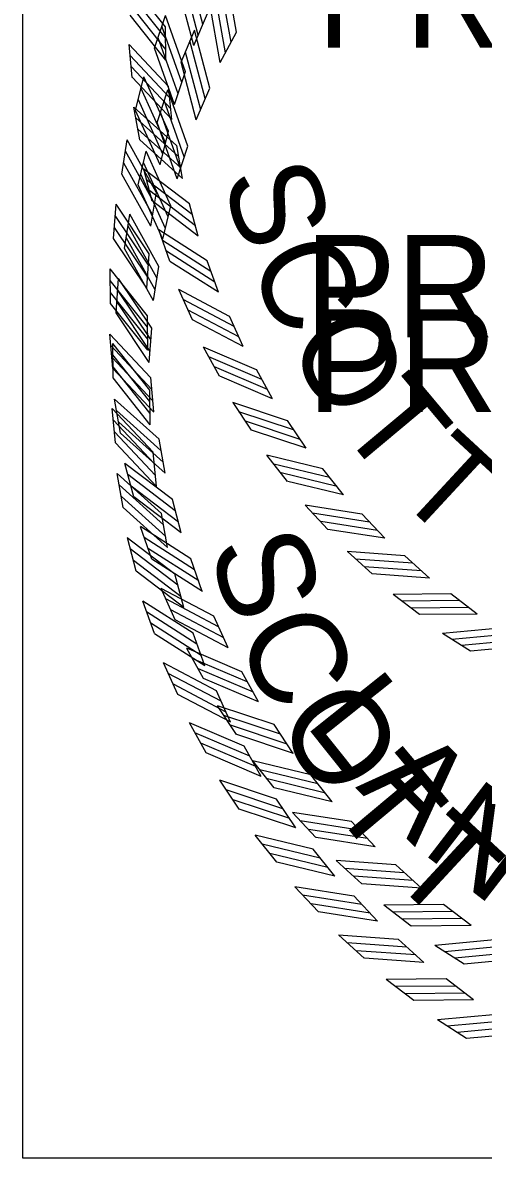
# Model space of a CAD drawing. Extents: x 0 to 1228740, y 0 to 152440.
# Drawn here: x 30.673 to 31.399, y 22.685 to 24.476 of the extents above; entities that cross this region are included whole.
import ezdxf

# ---------------------------------------------------------------- set-up
doc = ezdxf.new("R2010")
doc.units = 0
for name, color, linetype in [('R_No Plot', 7, 'Continuous'), ('STAMP_LKM', 7, 'Continuous'), ('STAMP_PP', 7, 'Continuous'), ('STAMP_SPT', 7, 'Continuous')]:
    doc.layers.add(name, color=color, linetype=linetype)

msp = doc.modelspace()

# ---------------------------------------------------------------- linework, layer by layer
at = {"layer": 'R_No Plot'}
msp.add_lwpolyline([(30.6731, 25.4352), (33.4231, 25.4352), (33.4231, 22.6852), (30.6731, 22.6852)], close=True, dxfattribs=at)
at = {"layer": 'STAMP_LKM'}
for p, q in [((30.8808, 24.4356), (30.898, 24.4872)), ((30.9426, 24.4399), (30.964, 24.49)), ((30.851, 24.3374), (30.8639, 24.3903)), ((30.9122, 24.3468), (30.9295, 24.3986)), ((30.8897, 24.2516), (30.9026, 24.3046)), ((30.8295, 24.2371), (30.8379, 24.2909)), ((30.8751, 24.1548), (30.8836, 24.2087)), ((30.8162, 24.1354), (30.8202, 24.1897)), ((30.8685, 24.0571), (30.8725, 24.1115)), ((30.8115, 24.033), (30.811, 24.0874)), ((30.8701, 23.9593), (30.8696, 24.0138)), ((30.8152, 23.9305), (30.8102, 23.9847)), ((30.8797, 23.8619), (30.8747, 23.9162)), ((30.8274, 23.8287), (30.8179, 23.8822)), ((30.8973, 23.7656), (30.8878, 23.8193)), ((30.8479, 23.7282), (30.8341, 23.7808)), ((30.9228, 23.6711), (30.9089, 23.7238)), ((30.8767, 23.6297), (30.8585, 23.681)), ((30.956, 23.579), (30.9378, 23.6305)), ((30.9135, 23.534), (30.8911, 23.5836)), ((30.9967, 23.49), (30.9743, 23.5398)), ((30.958, 23.4416), (30.9317, 23.4892)), ((31.0446, 23.4047), (31.0182, 23.4524)), ((31.0101, 23.3533), (30.9799, 23.3985)), ((31.0994, 23.3236), (31.0692, 23.369)), ((31.0692, 23.2695), (31.0354, 23.3121)), ((31.1607, 23.2473), (31.1269, 23.29)), ((31.1351, 23.1909), (31.0979, 23.2306)), ((31.2282, 23.1763), (31.1908, 23.2161)), ((31.2073, 23.118), (31.1669, 23.1545)), ((31.3012, 23.1112), (31.2607, 23.1477)), ((31.2852, 23.0513), (31.242, 23.0843)), ((31.3794, 23.0523), (31.336, 23.0854)), ((31.3684, 22.9913), (31.3225, 23.0206))]:
    msp.add_line(p, q, dxfattribs=at)
for points in [[(30.9567, 24.4734), (30.9326, 24.5644)], [(30.9426, 24.4398), (30.9186, 24.5308)], [(30.9496, 24.4558), (30.9256, 24.5469)], [(30.9294, 24.3985), (30.8979, 24.4872)], [(30.9235, 24.3814), (30.8921, 24.4701)], [(30.918, 24.3633), (30.8865, 24.452)], [(30.9123, 24.3467), (30.8808, 24.4355)], [(30.9025, 24.3045), (30.8639, 24.3903)], [(30.8981, 24.2869), (30.8594, 24.3728)], [(30.894, 24.2685), (30.8553, 24.3543)], [(30.8897, 24.2515), (30.851, 24.3373)], [(30.8835, 24.2086), (30.8379, 24.2909)], [(30.8805, 24.1907), (30.8349, 24.2731)], [(30.878, 24.172), (30.8324, 24.2543)], [(30.8751, 24.1547), (30.8295, 24.2371)], [(30.8725, 24.1115), (30.8202, 24.1898)], [(30.871, 24.0934), (30.8187, 24.1717)], [(30.87, 24.0745), (30.8177, 24.1528)], [(30.8686, 24.0571), (30.8163, 24.1354)], [(30.8695, 24.0137), (30.8109, 24.0874)], [(30.8695, 23.9956), (30.8109, 24.0693)], [(30.8701, 23.9767), (30.8115, 24.0504)], [(30.8701, 23.9592), (30.8115, 24.0329)], [(30.8746, 23.9161), (30.8102, 23.9847)], [(30.8761, 23.8981), (30.8117, 23.9667)], [(30.8783, 23.8793), (30.8138, 23.9479)], [(30.8797, 23.8618), (30.8153, 23.9304)], [(30.8878, 23.8192), (30.8179, 23.8823)], [(30.8908, 23.8014), (30.8209, 23.8644)], [(30.8945, 23.7828), (30.8246, 23.8459)], [(30.8973, 23.7655), (30.8274, 23.8286)], [(30.9089, 23.7238), (30.834, 23.7808)], [(30.9133, 23.7062), (30.8385, 23.7633)], [(30.9186, 23.688), (30.8437, 23.7451)], [(30.9228, 23.6711), (30.848, 23.7281)], [(30.9378, 23.6304), (30.8585, 23.6811)], [(30.9437, 23.6132), (30.8644, 23.6639)], [(30.9504, 23.5956), (30.8711, 23.6462)], [(30.9561, 23.579), (30.8767, 23.6297)], [(30.9743, 23.5397), (30.8911, 23.5837)], [(30.9816, 23.5231), (30.8984, 23.5671)], [(30.9898, 23.506), (30.9065, 23.55)], [(30.9968, 23.49), (30.9135, 23.534)], [(31.0182, 23.4523), (30.9316, 23.4893)], [(31.0269, 23.4364), (30.9403, 23.4733)], [(31.0364, 23.4201), (30.9498, 23.457)], [(31.0447, 23.4047), (30.9581, 23.4416)], [(31.0692, 23.3689), (30.9798, 23.3986)], [(31.0791, 23.3537), (30.9898, 23.3834)], [(31.0899, 23.3382), (31.0006, 23.3679)], [(31.0995, 23.3236), (31.0102, 23.3532)], [(31.1269, 23.29), (31.0354, 23.3121)], [(31.138, 23.2757), (31.0465, 23.2978)], [(31.1501, 23.2611), (31.0586, 23.2833)], [(31.1608, 23.2473), (31.0693, 23.2695)], [(31.1909, 23.216), (31.0979, 23.2306)], [(31.2031, 23.2027), (31.1101, 23.2173)], [(31.2164, 23.1892), (31.1234, 23.2038)], [(31.2282, 23.1763), (31.1352, 23.1909)], [(31.2607, 23.1477), (31.1669, 23.1545)], [(31.2741, 23.1354), (31.1802, 23.1422)], [(31.2884, 23.123), (31.1945, 23.1299)], [(31.3013, 23.1112), (31.2074, 23.118)], [(31.336, 23.0853), (31.2419, 23.0843)], [(31.3503, 23.0742), (31.2562, 23.0732)], [(31.3656, 23.063), (31.2715, 23.0621)], [(31.3794, 23.0523), (31.2853, 23.0513)], [(31.4162, 23.0294), (31.3225, 23.0206)], [(31.4314, 23.0195), (31.3377, 23.0107)], [(31.4475, 23.0096), (31.3538, 23.0009)], [(31.4622, 23), (31.3685, 22.9913)]]:
    msp.add_lwpolyline(points, dxfattribs=at)
at = {"layer": 'STAMP_PP'}
for p, q in [((30.8986, 24.4169), (30.8981, 24.4694)), ((30.8457, 24.3891), (30.8409, 24.4413)), ((30.9078, 24.323), (30.903, 24.3754)), ((30.8574, 24.2911), (30.8483, 24.3427)), ((30.9248, 24.2303), (30.9157, 24.282)), ((30.8772, 24.1943), (30.8639, 24.245)), ((30.9493, 24.1393), (30.936, 24.1901)), ((30.9049, 24.0995), (30.8875, 24.1489)), ((30.9813, 24.0506), (30.9638, 24.1002)), ((30.9404, 24.0073), (30.9189, 24.0551)), ((31.0205, 23.9649), (30.999, 24.0128)), ((30.9833, 23.9183), (30.9579, 23.9642)), ((31.0667, 23.8827), (31.0413, 23.9287)), ((31.0334, 23.8332), (31.0044, 23.8768)), ((31.1195, 23.8046), (31.0903, 23.8483)), ((31.0904, 23.7525), (31.0578, 23.7936)), ((31.1785, 23.7311), (31.1459, 23.7723)), ((31.1539, 23.6768), (31.118, 23.715)), ((31.2435, 23.6628), (31.2075, 23.7011)), ((31.2234, 23.6066), (31.1845, 23.6417)), ((31.3138, 23.6), (31.2748, 23.6352)), ((31.2984, 23.5424), (31.2568, 23.5742)), ((31.3891, 23.5433), (31.3473, 23.5752)), ((31.3785, 23.4846), (31.3344, 23.5128))]:
    msp.add_line(p, q, dxfattribs=at)
for points in [[(30.898, 24.4693), (30.8416, 24.5403)], [(30.898, 24.4519), (30.8416, 24.5228)], [(30.8986, 24.4337), (30.8422, 24.5046)], [(30.8986, 24.4168), (30.8422, 24.4878)], [(30.903, 24.3753), (30.8409, 24.4414)], [(30.9044, 24.3579), (30.8423, 24.424)], [(30.9065, 24.3398), (30.8444, 24.4059)], [(30.9079, 24.323), (30.8458, 24.3891)], [(30.9156, 24.282), (30.8483, 24.3427)], [(30.9185, 24.2648), (30.8512, 24.3255)], [(30.9221, 24.2469), (30.8547, 24.3076)], [(30.9248, 24.2303), (30.8575, 24.291)], [(30.936, 24.19), (30.8638, 24.245)], [(30.9402, 24.1731), (30.8681, 24.2281)], [(30.9453, 24.1556), (30.8731, 24.2106)], [(30.9494, 24.1393), (30.8773, 24.1942)], [(30.9638, 24.1001), (30.8874, 24.1489)], [(30.9695, 24.0836), (30.8931, 24.1324)], [(30.9759, 24.0665), (30.8995, 24.1154)], [(30.9814, 24.0506), (30.905, 24.0994)], [(30.999, 24.0127), (30.9188, 24.0551)], [(31.006, 23.9968), (30.9258, 24.0391)], [(31.0138, 23.9803), (30.9337, 24.0227)], [(31.0206, 23.9649), (30.9404, 24.0072)], [(31.0413, 23.9286), (30.9579, 23.9642)], [(31.0496, 23.9133), (30.9662, 23.9488)], [(31.0587, 23.8975), (30.9753, 23.9331)], [(31.0668, 23.8827), (30.9834, 23.9183)], [(31.0904, 23.8482), (31.0043, 23.8768)], [(31.0999, 23.8336), (31.0138, 23.8622)], [(31.1103, 23.8187), (31.0243, 23.8473)], [(31.1196, 23.8046), (31.0335, 23.8332)], [(31.1459, 23.7722), (31.0578, 23.7936)], [(31.1566, 23.7584), (31.0685, 23.7798)], [(31.1683, 23.7444), (31.0801, 23.7658)], [(31.1786, 23.7311), (31.0905, 23.7525)], [(31.2075, 23.701), (31.118, 23.715)], [(31.2194, 23.6882), (31.1298, 23.7022)], [(31.2321, 23.6752), (31.1425, 23.6892)], [(31.2435, 23.6628), (31.1539, 23.6768)], [(31.2748, 23.6352), (31.1844, 23.6417)], [(31.2877, 23.6234), (31.1973, 23.6299)], [(31.3015, 23.6114), (31.211, 23.618)], [(31.3139, 23.6), (31.2234, 23.6066)], [(31.3474, 23.5751), (31.2567, 23.5742)], [(31.3611, 23.5644), (31.2705, 23.5635)], [(31.3758, 23.5537), (31.2852, 23.5527)], [(31.3892, 23.5433), (31.2985, 23.5424)], [(31.4246, 23.5212), (31.3343, 23.5128)], [(31.4392, 23.5117), (31.3489, 23.5033)], [(31.4547, 23.5022), (31.3645, 23.4938)], [(31.4689, 23.493), (31.3786, 23.4846)]]:
    msp.add_lwpolyline(points, dxfattribs=at)
at = {"layer": 'STAMP_SPT'}
for p, q in [((30.9225, 24.4136), (30.9439, 24.4636)), ((30.9844, 24.4128), (31.0099, 24.461)), ((30.8847, 24.3182), (30.9019, 24.3698)), ((30.9465, 24.3225), (30.968, 24.3727)), ((30.9162, 24.2295), (30.9334, 24.2812)), ((30.8549, 24.2201), (30.8678, 24.2729)), ((30.8334, 24.1198), (30.8418, 24.1735)), ((30.8936, 24.1342), (30.9065, 24.1872)), ((30.879, 24.0375), (30.8875, 24.0913)), ((30.8202, 24.0181), (30.8242, 24.0724)), ((30.8725, 23.9398), (30.8765, 23.9942)), ((30.8154, 23.9156), (30.8149, 23.9701)), ((30.874, 23.8419), (30.8735, 23.8965)), ((30.8191, 23.8132), (30.8141, 23.8673)), ((30.8836, 23.7445), (30.8786, 23.7988)), ((30.8313, 23.7113), (30.8219, 23.7649)), ((30.9012, 23.6483), (30.8917, 23.702)), ((30.8518, 23.6108), (30.838, 23.6635)), ((30.9267, 23.5538), (30.9128, 23.6065)), ((30.8806, 23.5124), (30.8625, 23.5637)), ((30.9599, 23.4617), (30.9418, 23.5131)), ((30.9174, 23.4167), (30.8951, 23.4663)), ((31.0006, 23.3727), (30.9783, 23.4224)), ((30.962, 23.3243), (30.9356, 23.3719)), ((31.0486, 23.2873), (31.0222, 23.3351)), ((31.014, 23.2359), (30.9838, 23.2812)), ((31.1034, 23.2063), (31.0731, 23.2516)), ((31.0732, 23.1522), (31.0394, 23.1948)), ((31.1647, 23.13), (31.1308, 23.1727)), ((31.1391, 23.0736), (31.1019, 23.1132)), ((31.2321, 23.059), (31.1948, 23.0988)), ((31.2112, 23.0007), (31.1709, 23.0371)), ((31.3051, 22.9938), (31.2647, 23.0304)), ((31.2891, 22.934), (31.2459, 22.967)), ((31.3833, 22.9349), (31.3399, 22.968)), ((31.3723, 22.874), (31.3265, 22.9033))]:
    msp.add_line(p, q, dxfattribs=at)
for points in [[(31.0099, 24.4609), (30.9934, 24.5536)], [(31.0013, 24.445), (30.9848, 24.5377)], [(30.9928, 24.4281), (30.9763, 24.5208)], [(30.9844, 24.4127), (30.968, 24.5054)], [(30.9679, 24.3726), (30.9439, 24.4637)], [(30.9606, 24.356), (30.9366, 24.4471)], [(30.9536, 24.3385), (30.9295, 24.4295)], [(30.9465, 24.3225), (30.9225, 24.4135)], [(30.9334, 24.2812), (30.9019, 24.3699)], [(30.9275, 24.264), (30.896, 24.3528)], [(30.9219, 24.246), (30.8904, 24.3347)], [(30.9162, 24.2294), (30.8847, 24.3181)], [(30.9065, 24.1872), (30.8678, 24.273)], [(30.902, 24.1696), (30.8633, 24.2554)], [(30.898, 24.1511), (30.8593, 24.237)], [(30.8937, 24.1342), (30.855, 24.22)], [(30.8875, 24.0913), (30.8418, 24.1736)], [(30.8845, 24.0734), (30.8388, 24.1557)], [(30.882, 24.0547), (30.8363, 24.137)], [(30.8791, 24.0374), (30.8334, 24.1197)], [(30.8764, 23.9941), (30.8241, 24.0724)], [(30.8749, 23.9761), (30.8226, 24.0543)], [(30.874, 23.9572), (30.8217, 24.0355)], [(30.8725, 23.9397), (30.8202, 24.018)], [(30.8735, 23.8964), (30.8149, 23.9701)], [(30.8735, 23.8783), (30.8149, 23.952)], [(30.8741, 23.8594), (30.8155, 23.9331)], [(30.8741, 23.8419), (30.8155, 23.9156)], [(30.8786, 23.7988), (30.8141, 23.8674)], [(30.8801, 23.7807), (30.8156, 23.8493)], [(30.8822, 23.7619), (30.8177, 23.8305)], [(30.8837, 23.7445), (30.8192, 23.8131)], [(30.8917, 23.7019), (30.8218, 23.7649)], [(30.8947, 23.684), (30.8248, 23.7471)], [(30.8984, 23.6655), (30.8285, 23.7285)], [(30.9013, 23.6482), (30.8314, 23.7113)], [(30.9128, 23.6064), (30.8379, 23.6635)], [(30.9173, 23.5889), (30.8424, 23.6459)], [(30.9225, 23.5707), (30.8476, 23.6278)], [(30.9268, 23.5537), (30.8519, 23.6108)], [(30.9417, 23.513), (30.8624, 23.5637)], [(30.9476, 23.4959), (30.8683, 23.5466)], [(30.9543, 23.4782), (30.875, 23.5289)], [(30.96, 23.4617), (30.8807, 23.5123)], [(30.9783, 23.4224), (30.895, 23.4663)], [(30.9856, 23.4058), (30.9023, 23.4497)], [(30.9937, 23.3887), (30.9104, 23.4327)], [(31.0007, 23.3727), (30.9175, 23.4166)], [(31.0222, 23.335), (30.9356, 23.3719)], [(31.0308, 23.3191), (30.9442, 23.356)], [(31.0403, 23.3027), (30.9537, 23.3397)], [(31.0486, 23.2873), (30.962, 23.3243)], [(31.0731, 23.2516), (30.9838, 23.2812)], [(31.083, 23.2364), (30.9937, 23.266)], [(31.0939, 23.2209), (31.0045, 23.2505)], [(31.1034, 23.2062), (31.0141, 23.2359)], [(31.1308, 23.1726), (31.0393, 23.1948)], [(31.1419, 23.1583), (31.0504, 23.1805)], [(31.154, 23.1438), (31.0625, 23.1659)], [(31.1648, 23.1299), (31.0733, 23.1521)], [(31.1948, 23.0987), (31.1018, 23.1133)], [(31.2071, 23.0854), (31.1141, 23.0999)], [(31.2203, 23.0719), (31.1273, 23.0864)], [(31.2322, 23.059), (31.1392, 23.0735)], [(31.2647, 23.0303), (31.1708, 23.0372)], [(31.278, 23.0181), (31.1841, 23.0249)], [(31.2923, 23.0057), (31.1984, 23.0125)], [(31.3052, 22.9938), (31.2113, 23.0007)], [(31.34, 22.968), (31.2458, 22.967)], [(31.3543, 22.9568), (31.2601, 22.9559)], [(31.3695, 22.9457), (31.2754, 22.9447)], [(31.3834, 22.9349), (31.2892, 22.934)], [(31.4202, 22.912), (31.3264, 22.9033)], [(31.4353, 22.9021), (31.3416, 22.8934)], [(31.4515, 22.8923), (31.3577, 22.8835)], [(31.4661, 22.8827), (31.3724, 22.874)]]:
    msp.add_lwpolyline(points, dxfattribs=at)

# ---------------------------------------------------------------- texts
at = {"layer": 'STAMP_LKM'}
msp.add_text('PROFESSIONAL', height=0.161547, dxfattribs=at).set_placement((31.1173, 23.9794))
for s, rotation, p in [('L', 308.5467, (31.116, 23.371)), ('A', 315.1131, (31.1964, 23.27)), ('N', 322.4091, (31.2986, 23.1695))]:
    msp.add_text(s, height=0.1504, rotation=rotation, dxfattribs=at).set_placement(p)
at = {"layer": 'STAMP_PP'}
msp.add_text('PROFESSIONAL', height=0.155591, dxfattribs=at).set_placement((31.1367, 24.4362))
for s, rotation, p in [('S', 286.9475, (30.9864, 24.2319)), ('C', 294.2435, (31.0267, 24.0998)), ('O', 301.9044, (31.0866, 23.9678)), ('T', 309.93, (31.1677, 23.8394)), ('T', 317.226, (31.2564, 23.7335))]:
    msp.add_text(s, height=0.1448, rotation=rotation, dxfattribs=at).set_placement(p)
at = {"layer": 'STAMP_SPT'}
msp.add_text('PROFESSIONAL', height=0.161547, dxfattribs=at).set_placement((31.1213, 23.862))
for s, rotation, p in [('S', 286.9475, (30.9652, 23.6499)), ('C', 294.2435, (31.007, 23.5128)), ('O', 301.9044, (31.0693, 23.3757)), ('T', 309.93, (31.1535, 23.2424)), ('T', 317.226, (31.2455, 23.1325))]:
    msp.add_text(s, height=0.1503, rotation=rotation, dxfattribs=at).set_placement(p)

doc.saveas('drawing.dxf')
